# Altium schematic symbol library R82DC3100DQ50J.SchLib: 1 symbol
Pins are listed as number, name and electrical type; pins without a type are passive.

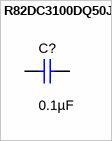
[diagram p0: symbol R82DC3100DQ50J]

## R82DC3100DQ50J
designator C?  ValueDisplayed: 0.1µF  (hidden comment: R82DC3100DQ50J)
CAP, Film, 0.1 µF, 63 V, +/- 5%, TH; Manufacturer: Kemet; Polarized: N; CompType: Capacitor; Value: 0.1uF; U/M: EA; Cap_F: 0.0000001; Tolerance_%: 5; Value1: Unknown; VDC_V: 63; Value2: 63V; TaMin_C: -55; TaMax_C: 105; Cap_Case: 7.2x2.5x6.5mm; AEC Category: Q200
signal-integrity model Cap
simulation model Cap
footprint R82_720x250x650
pins: 1, 2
